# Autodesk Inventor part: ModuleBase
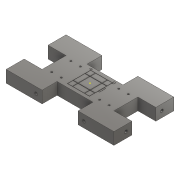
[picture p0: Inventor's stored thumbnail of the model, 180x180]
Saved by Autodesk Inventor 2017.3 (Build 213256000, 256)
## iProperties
Part Number: ModuleBase
Material: ステンレス鋼
Document SubType Name: Modeling
Designer: kyushu-hep
Density: 8 g/cm^3
Appearance: 半つや出し
Mass: 96.9479 g
Surface Area: 172.882 cm^2
Volume: 104.245 cm^3
Author: kyushu-hep
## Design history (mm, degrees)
sketch "スケッチ1"
  geometry: L1 (-90, 50)-(90, 50); L2 (90, 50)-(90, -50); L3 (90, -50)-(-90, -50); L4 (-90, -50)-(-90, 50); 1 further point
  constraints: 8 end point, 2 parallel, 1 horizontal, 1 perpendicular
  dimensions: "d0" = 180 distance of L2.end L3.end; "d1" = 100 distance of L1.end L2.end; "d22" = 50 distance from line of point (0, 0) L3; "d23" = 90 distance from line of L2 point (0, 0)
extrude "押し出し1" new body sketch "スケッチ1" distance "d2" = 20; taper "d3" = 0 deg
sketch "スケッチ4"
  geometry: L1 (17.855, 22.225)-(17.855, 20.225); L2 (17.855, 20.225)-(19.055, 20.225); L3 (19.055, 20.225)-(19.055, 18.225); L4 (19.055, 18.225)-(21.055, 18.225); L5 (21.055, 18.225)-(21.055, 22.225); L6 (21.055, 22.225)-(17.855, 22.225); L7 (21.055, 5)-(21.055, -5); L8 (21.055, -5)-(19.055, -5); L9 (19.055, -5)-(19.055, 5); L10 (19.055, 5)-(21.055, 5); L11 (-90, -50)-(90, -50) reference; L12 (-90, 50)-(-90, -50) reference; L13 (-21.055, 22.225)-(-17.855, 22.225); L14 (-17.855, 22.225)-(-17.855, 20.225); L15 (-17.855, 20.225)-(-21.055, 20.225); L16 (-21.055, 20.225)-(-21.055, 22.225); 1 further point
  constraints: 28 end point, 8 perpendicular, 4 point on line, 2 parallel, 1 collinear, 1 horizontal, 1 vertical
  dimensions: "d12" = 2 distance of L1.start L1.end; "d13" = 1.2 distance of L1.end L2.end; "d14" = 2 distance of L2.end L3.end; "d15" = 2 distance of L3.end L4.end; "d16" = 10 distance of L7.start L7.end; "d24" = 19.055 distance from line of L9 point (0, 0); "d25" = 22.225 distance from line of point (0, 0) L6; "d28" = 17.855 distance from line of point (0, 0) L14
extrude "押し出し4" join sketch "スケッチ4" distance "d29" = 0.3; taper "d30" = 0 deg
sketch "スケッチ6"
  geometry: L1 (20, 20)-(-20, 20); L2 (-20, 20)-(-20, -20); L3 (-20, -20)-(20, -20); L4 (20, -20)-(20, 20); L5 (20, 20)-(-20, -20); L6 (-20, 20)-(20, -20); C1 r 1.5 at (-16, -16); C2 r 1.5 at (-16, 16); C3 r 1.5 at (16, -16); C4 r 1.5 at (16, 16); 1 further point
  constraints: 12 end point, 4 centre point, 2 horizontal, 2 midpoint, 2 parallel, 1 perpendicular, 1 vertical, 6 other
  dimensions: "d41" = 3 diameter of C1; "d42" = 16 horizontal distance of point (0, 0) C1.centre; "d43" = 16 horizontal distance of point (0, 0) C1.centre; "d44" = 40 distance of L3.end L2.end; "d45" = 40 distance of L2.end L1.end; "d48" = 32 distance of C1.centre C2.centre; "d51" = 32 distance of C1.centre C3.centre
sketch "スケッチ7"
  geometry: C1 r 0.5 at (-10, 10); C2 r 0.5 at (10, 10); C3 r 0.5 at (-10, -10); C4 r 0.5 at (10, -10); 1 further point
  constraints: 4 centre point
  dimensions: "d58" = 1 diameter of C1; "d59" = 10 horizontal distance of point (0, 0) C1.centre; "d60" = 10 horizontal distance of point (0, 0) C1.centre; "d61" = 1 diameter of C2; "d62" = 10 horizontal distance of point (0, 0) C2.centre; "d63" = 1 diameter of C3; "d64" = 10 horizontal distance of point (0, 0) C3.centre; "d65" = 1 diameter of C4
extrude "押し出し9" cut sketch "スケッチ7" distance "d66" = 10; taper "d67" = 0 deg
sketch "スケッチ9"
  geometry: L1 (18.5, -19.5)-(-18.5, -19.5); L2 (-18.5, -19.5)-(-18.5, 19.5); L3 (-18.5, 19.5)-(18.5, 19.5); L4 (18.5, 19.5)-(18.5, -19.5); L5 (18.5, -19.5)-(-18.5, 19.5); L6 (-18.5, -19.5)-(18.5, 19.5); L7 (-10.5, 10.5)-(-18, 10.5); L8 (-18, 10.5)-(-18, 19); L9 (-18, 19)-(-10.5, 19); L10 (-10.5, 19)-(-10.5, 10.5); L11 (-10.5, 10.5)-(-18, 19); L12 (-18, 10.5)-(-10.5, 19); L13 (18, 10.5)-(10.5, 10.5); L14 (10.5, 10.5)-(10.5, 19); L15 (10.5, 19)-(18, 19); L16 (18, 19)-(18, 10.5); L17 (-9.5, 19)-(9.5, 19); L18 (9.5, 19)-(9.5, 10.5); L19 (9.5, 10.5)-(-9.5, 10.5); L20 (-9.5, 10.5)-(-9.5, 19); L21 (-18, 9.5)-(-10.5, 9.5); L22 (-10.5, 9.5)-(-10.5, -9.5); L23 (-10.5, -9.5)-(-18, -9.5); L24 (-18, -9.5)-(-18, 9.5); L25 (-18, -10.5)-(-10.5, -10.5); L26 (-10.5, -10.5)-(-10.5, -19); L27 (-10.5, -19)-(-18, -19); L28 (-18, -19)-(-18, -10.5); L29 (-9.5, 9.5)-(9.5, 9.5); L30 (9.5, 9.5)-(9.5, -9.5); L31 (9.5, -9.5)-(-9.5, -9.5); L32 (-9.5, -9.5)-(-9.5, 9.5); L33 (10.5, 9.5)-(18, 9.5); L34 (18, 9.5)-(18, -9.5); L35 (18, -9.5)-(10.5, -9.5); L36 (10.5, -9.5)-(10.5, 9.5); L37 (-9.5, -10.5)-(9.5, -10.5); L38 (9.5, -10.5)-(9.5, -19); L39 (9.5, -19)-(-9.5, -19); L40 (-9.5, -19)-(-9.5, -10.5); L41 (10.5, -10.5)-(18, -10.5); L42 (18, -10.5)-(18, -19); L43 (18, -19)-(10.5, -19); L44 (10.5, -19)-(10.5, -10.5); 2 further points
  constraints: 88 end point, 20 parallel, 19 collinear, 10 horizontal, 10 perpendicular, 4 midpoint, 4 point on line
  dimensions: "d78" = 37 distance of L2.end L3.end; "d79" = 39 distance of L1.end L2.end; "d80" = 7.5 distance of L8.end L9.end; "d81" = 0.5 distance between parallel lines of L3 L9; "d82" = 0.5 distance between parallel lines of L2 L8; "d83" = 8.5 distance of L7.end L8.end; "d88" = 19 distance of L18.end L19.end; "d89" = 8.5 distance of L17.end L18.end; "d90" = 1 distance between parallel lines of L10 L20; "d92" = 19 distance of L21.end L22.end; "d93" = 1 distance between parallel lines of L21 L7; "d94" = 8.5 distance of L25.end L26.end; "d95" = 1 distance between parallel lines of L25 L23; "d96" = 8.5 distance of L13.end L14.end; "d97" = 1 distance between parallel lines of L14 L18
extrude "押し出し11" cut sketch "スケッチ9" distance "d98" = 1; taper "d99" = 0 deg
extrude "押し出し13" cut sketch "スケッチ6" distance "d102" = 10; taper "d103" = 0 deg
sketch "スケッチ10"
  geometry: 1 further point
sketch "スケッチ11"
  geometry: L1 (20, 20)-(-20, 20); L2 (-20, 20)-(-20, -20); L3 (-20, -20)-(20, -20); L4 (20, -20)-(20, 20); L5 (20, 20)-(-20, -20); L6 (-20, 20)-(20, -20); C1 r 1.5 at (-48, -16); C2 r 1.5 at (-48, 16); C3 r 1.5 at (-32, -16); C4 r 1.5 at (-32, 16); C5 r 1.5 at (-16, -16); C6 r 1.5 at (-16, 16); C7 r 1.5 at (0, -16); C8 r 1.5 at (0, 16); C9 r 1.5 at (16, -16); C10 r 1.5 at (16, 16); C11 r 1.5 at (32, -16); C12 r 1.5 at (32, 16); C13 r 1.5 at (48, -16); C14 r 1.5 at (48, 16); 3 further points
  constraints: 14 centre point, 12 end point, 2 horizontal, 2 midpoint, 2 parallel, 1 perpendicular, 1 vertical, 26 other
  dimensions: "d108" = 3 diameter of C1; "d109" = 48 horizontal distance of point (0, 0) C1.centre; "d110" = 16 vertical distance of point (0, 0) C1.centre; "d111" = 40 distance of L3.end L2.end; "d112" = 40 distance of L2.end L1.end; "d113" = 32 distance of C1.centre C2.centre; "d114" = 16 distance of C1.centre C3.centre
extrude "押し出し14" cut sketch "スケッチ11" distance "d115" = 10; taper "d116" = 0 deg
sketch "スケッチ12"
  geometry: C1 r 2.5 at (10, 80); C2 r 2.5 at (10, 20); 1 further point
  constraints: 2 centre point
  dimensions: "d117" = 5 diameter of C1; "d118" = 30 vertical distance of point (0, 50) C1.centre; "d119" = 10 horizontal distance of point (0, 50) C1.centre; "d120" = 5 diameter of C2; "d121" = 30 vertical distance of C2.centre point (0, 50); "d122" = 10 horizontal distance of point (0, 50) C2.centre
extrude "押し出し15" cut sketch "スケッチ12" distance "d123" = 10; taper "d124" = 0 deg
sketch "スケッチ13"
  geometry: C1 r 2.5 at (-10, 20); C2 r 2.5 at (-10, 80); 1 further point
  constraints: 2 centre point
  dimensions: "d125" = 5 diameter of C1; "d126" = 5 diameter of C2; "d127" = 10 horizontal distance of point (0, 50) C1.centre; "d128" = 30 vertical distance of point (0, 50) C1.centre; "d129" = 30 vertical distance of C2.centre point (0, 50); "d130" = 10 horizontal distance of C2.centre point (0, 50)
extrude "押し出し16" cut sketch "スケッチ13" distance "d131" = 10; taper "d132" = 0 deg
sketch "スケッチ14"
  geometry: C1 r 2.5 at (50, 10); C2 r 2.5 at (130, 10); 1 further point
  constraints: 2 centre point
  dimensions: "d133" = 5 diameter of C1; "d134" = 5 diameter of C2; "d135" = 10 vertical distance of point (90, 0) C1.centre; "d136" = 40 horizontal distance of point (90, 0) C1.centre; "d137" = 40 horizontal distance of C2.centre point (90, 0); "d138" = 10 vertical distance of point (90, 0) C2.centre
extrude "押し出し17" cut sketch "スケッチ14" distance "d139" = 10; taper "d140" = 0 deg
sketch "スケッチ15"
  geometry: C1 r 2.5 at (130, -10); C2 r 2.5 at (50, -10); 1 further point
  constraints: 2 centre point
  dimensions: "d141" = 5 diameter of C1; "d142" = 5 diameter of C2; "d143" = 40 horizontal distance of point (90, 0) C1.centre; "d144" = 40 horizontal distance of point (90, 0) C2.centre; "d145" = 10 vertical distance of point (90, 0) C1.centre; "d146" = 10 vertical distance of C2.centre point (90, 0)
extrude "押し出し18" cut sketch "スケッチ15" distance "d147" = 10; taper "d148" = 0 deg
feature "ねじ1" dims "d149" = 10, "d150" = 0
feature "ねじ2" dims "d151" = 10, "d152" = 0
feature "ねじ3" dims "d153" = 10, "d154" = 0
feature "ねじ4" dims "d155" = 10, "d156" = 0
feature "ねじ5" dims "d157" = 10, "d158" = 0
feature "ねじ6" dims "d159" = 10, "d160" = 0
feature "ねじ7" dims "d161" = 10, "d162" = 0
feature "ねじ8" dims "d163" = 10, "d164" = 0
sketch "スケッチ16"
  geometry: L1 (90, 50)-(-90, 50) reference; L2 (-30, 50)-(30, 50); L3 (30, 50)-(30, 25); L4 (30, 25)-(-30, 25); L5 (-30, 25)-(-30, 50); L6 (-30, -50)-(30, -50); L7 (30, -50)-(30, -25); L8 (30, -25)-(-30, -25); L9 (-30, -25)-(-30, -50); 1 further point
  constraints: 16 end point, 4 parallel, 2 horizontal, 2 perpendicular, 1 point on line
  dimensions: "d165" = 60 distance of L3.end L4.end; "d166" = 25 distance of L2.end L3.end; "d169" = 60 distance of L8.end L7.end; "d170" = 25 distance of L7.end L6.end; "d171" = 25 distance from line of L8 point (0, 0); "d172" = 30 distance from line of point (0, 0) L9; "d173" = 30 distance from line of L5 point (0, 0)
extrude "押し出し20" cut sketch "スケッチ16" distance "d174" = 20; taper "d175" = 0 deg
sketch "スケッチ17"
  geometry: L1 (-90, -50)-(-90, 50) reference; L2 (-90, 20)-(-60, 20); L3 (-60, 20)-(-60, -20); L4 (-60, -20)-(-90, -20); L5 (-90, -20)-(-90, 20); L6 (90, 50)-(90, -50) reference; L7 (90, -20)-(60, -20); L8 (60, -20)-(60, 20); L9 (60, 20)-(90, 20); L10 (90, 20)-(90, -20); 1 further point
  constraints: 16 end point, 4 parallel, 2 horizontal, 2 perpendicular, 2 point on line
  dimensions: "d176" = 30 distance of L3.end L4.end; "d177" = 20 distance from line of point (0, 0) L2; "d178" = 40 distance of L2.end L3.end; "d179" = 30 distance of L8.end L9.end; "d180" = 40 distance of L7.end L8.end
extrude "押し出し21" cut sketch "スケッチ17" distance "d181" = 20; taper "d182" = 0 deg
node "ソリッド1"
